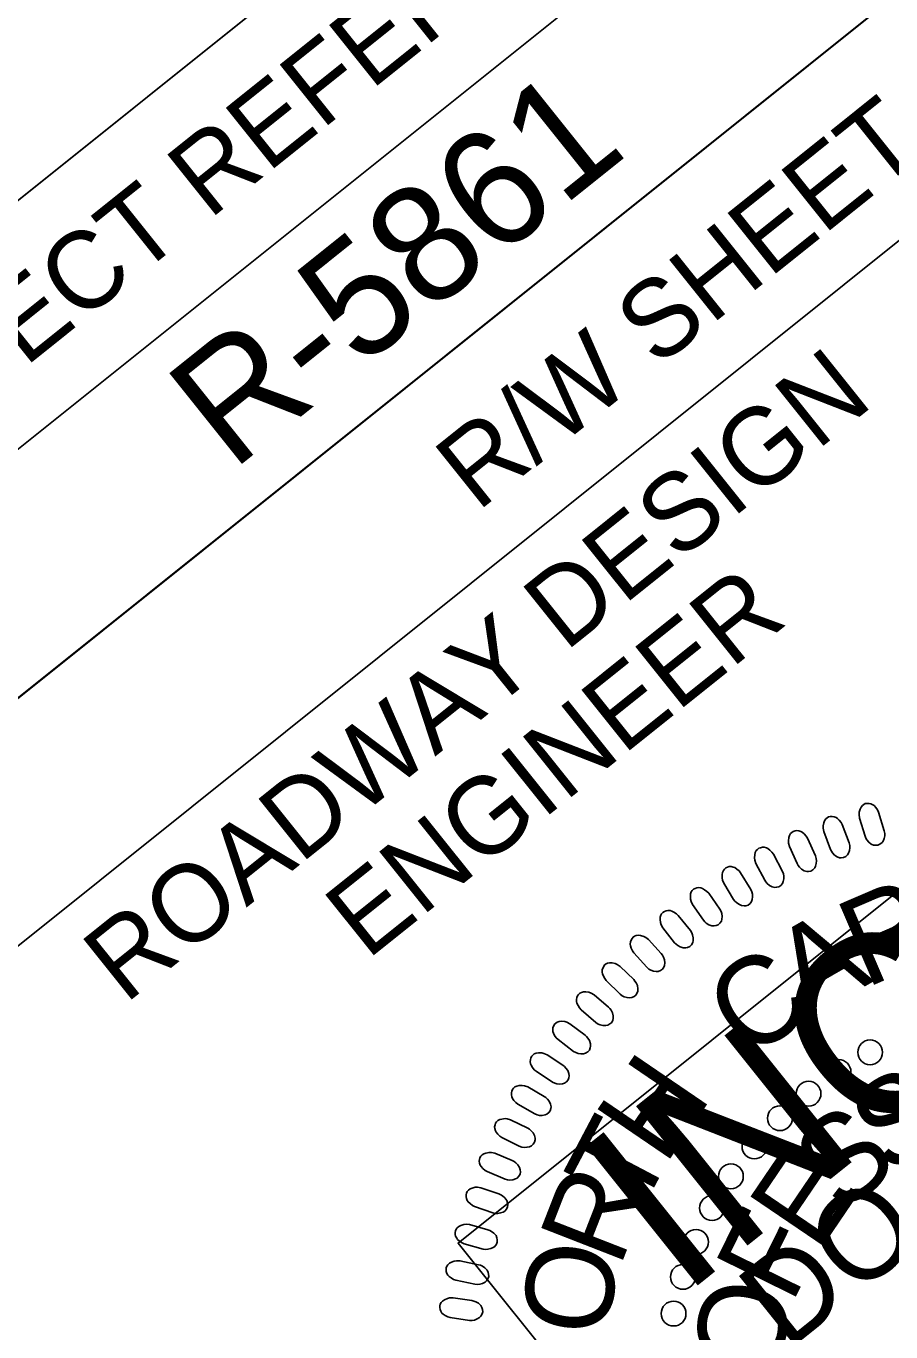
# Model space of a CAD drawing. Extents: x 472510 to 474509, y 505091 to 506998.
# Drawn here: x 473706 to 473761.9, y 506800.9 to 506885.2 of the extents above; entities that cross this region are included whole.
import ezdxf

# ---------------------------------------------------------------- set-up
doc = ezdxf.new("R2010")
doc.units = 0
for name, color, linetype in [('Sheet Data Field CELL', 7, 'Continuous'), ('Sheet PE Seal Cell', 7, 'Continuous'), ('Sheet Plan CELL', 7, 'Continuous'), ('Sheet Sticker Incomplete CELL', 7, 'Continuous')]:
    doc.layers.add(name, color=color, linetype=linetype)

msp = doc.modelspace()

# ---------------------------------------------------------------- linework, layer by layer
at = {"layer": 'Sheet PE Seal Cell'}
for points in [[(473760.213, 506832.902), (473759.853, 506834.074), (473759.824, 506834.295), (473759.833, 506834.444), (473759.891, 506834.639), (473759.952, 506834.773), (473760.035, 506834.882), (473760.124, 506834.95), (473760.225, 506835.003), (473760.338, 506835.016), (473760.461, 506835.023), (473760.579, 506834.996), (473760.708, 506834.931), (473760.789, 506834.873), (473760.897, 506834.75), (473761.007, 506834.596), (473761.075, 506834.45), (473761.451, 506833.25), (473761.478, 506833.081), (473761.477, 506832.935), (473761.438, 506832.756), (473761.372, 506832.589), (473761.303, 506832.485), (473761.169, 506832.382), (473761.032, 506832.319), (473760.878, 506832.313), (473760.763, 506832.33), (473760.612, 506832.388), (473760.449, 506832.516), (473760.331, 506832.667), (473760.265, 506832.783)], [(473757.971, 506832.049), (473757.538, 506833.197), (473757.496, 506833.416), (473757.496, 506833.564), (473757.54, 506833.763), (473757.593, 506833.899), (473757.669, 506834.014), (473757.753, 506834.088), (473757.851, 506834.146), (473757.963, 506834.167), (473758.086, 506834.181), (473758.205, 506834.162), (473758.338, 506834.106), (473758.422, 506834.052), (473758.538, 506833.936), (473758.657, 506833.789), (473758.734, 506833.648), (473759.184, 506832.474), (473759.224, 506832.308), (473759.23, 506832.161), (473759.203, 506831.98), (473759.147, 506831.81), (473759.084, 506831.701), (473758.959, 506831.59), (473758.825, 506831.519), (473758.672, 506831.503), (473758.556, 506831.513), (473758.402, 506831.561), (473758.231, 506831.678), (473758.104, 506831.822), (473758.031, 506831.933)], [(473755.826, 506831.129), (473755.321, 506832.247), (473755.266, 506832.462), (473755.256, 506832.611), (473755.288, 506832.812), (473755.332, 506832.952), (473755.401, 506833.07), (473755.48, 506833.15), (473755.574, 506833.215), (473755.685, 506833.242), (473755.806, 506833.264), (473755.926, 506833.252), (473756.062, 506833.204), (473756.149, 506833.156), (473756.273, 506833.047), (473756.401, 506832.908), (473756.488, 506832.772), (473757.01, 506831.629), (473757.059, 506831.466), (473757.075, 506831.32), (473757.059, 506831.138), (473757.014, 506830.964), (473756.959, 506830.851), (473756.84, 506830.732), (473756.712, 506830.653), (473756.559, 506830.628), (473756.443, 506830.63), (473756.287, 506830.669), (473756.107, 506830.774), (473755.973, 506830.911), (473755.892, 506831.016)], [(473753.729, 506830.058), (473753.157, 506831.143), (473753.087, 506831.354), (473753.068, 506831.502), (473753.088, 506831.704), (473753.123, 506831.846), (473753.184, 506831.969), (473753.258, 506832.053), (473753.348, 506832.124), (473753.456, 506832.158), (473753.576, 506832.188), (473753.697, 506832.184), (473753.836, 506832.144), (473753.926, 506832.102), (473754.055, 506832.001), (473754.192, 506831.87), (473754.287, 506831.739), (473754.881, 506830.632), (473754.939, 506830.472), (473754.965, 506830.327), (473754.96, 506830.144), (473754.926, 506829.968), (473754.878, 506829.853), (473754.767, 506829.726), (473754.644, 506829.639), (473754.494, 506829.604), (473754.378, 506829.6), (473754.219, 506829.628), (473754.034, 506829.723), (473753.89, 506829.849), (473753.803, 506829.951)], [(473751.724, 506828.82), (473751.084, 506829.866), (473751.001, 506830.073), (473750.973, 506830.219), (473750.98, 506830.422), (473751.006, 506830.567), (473751.06, 506830.693), (473751.128, 506830.782), (473751.214, 506830.858), (473751.32, 506830.899), (473751.437, 506830.936), (473751.558, 506830.939), (473751.699, 506830.909), (473751.792, 506830.872), (473751.928, 506830.78), (473752.072, 506830.657), (473752.174, 506830.533), (473752.837, 506829.465), (473752.906, 506829.309), (473752.94, 506829.167), (473752.947, 506828.984), (473752.924, 506828.806), (473752.883, 506828.687), (473752.78, 506828.554), (473752.663, 506828.459), (473752.515, 506828.415), (473752.4, 506828.403), (473752.239, 506828.421), (473752.048, 506828.504), (473751.898, 506828.622), (473751.804, 506828.717)], [(473749.77, 506827.48), (473749.065, 506828.485), (473748.97, 506828.686), (473748.933, 506828.83), (473748.927, 506829.033), (473748.944, 506829.179), (473748.99, 506829.309), (473749.053, 506829.401), (473749.133, 506829.482), (473749.236, 506829.53), (473749.351, 506829.574), (473749.471, 506829.586), (473749.614, 506829.564), (473749.709, 506829.533), (473749.85, 506829.449), (473750.002, 506829.337), (473750.112, 506829.219), (473750.84, 506828.194), (473750.919, 506828.043), (473750.962, 506827.903), (473750.98, 506827.721), (473750.969, 506827.542), (473750.935, 506827.421), (473750.841, 506827.281), (473750.73, 506827.179), (473750.585, 506827.126), (473750.47, 506827.107), (473750.309, 506827.116), (473750.114, 506827.186), (473749.956, 506827.294), (473749.857, 506827.383)], [(473747.912, 506826.027), (473747.145, 506826.985), (473747.038, 506827.18), (473746.991, 506827.322), (473746.973, 506827.524), (473746.98, 506827.67), (473747.018, 506827.803), (473747.075, 506827.899), (473747.15, 506827.985), (473747.25, 506828.039), (473747.362, 506828.091), (473747.481, 506828.109), (473747.625, 506828.097), (473747.722, 506828.071), (473747.868, 506827.997), (473748.027, 506827.894), (473748.144, 506827.783), (473748.934, 506826.807), (473749.023, 506826.661), (473749.075, 506826.523), (473749.105, 506826.343), (473749.105, 506826.163), (473749.078, 506826.041), (473748.993, 506825.896), (473748.889, 506825.787), (473748.747, 506825.725), (473748.635, 506825.698), (473748.473, 506825.696), (473748.273, 506825.755), (473748.109, 506825.853), (473748.004, 506825.935)], [(473747.047, 506825.323), (473746.222, 506826.231), (473746.046, 506826.368), (473745.914, 506826.436), (473745.717, 506826.487), (473745.571, 506826.503), (473745.434, 506826.486), (473745.33, 506826.446), (473745.234, 506826.384), (473745.165, 506826.294), (473745.096, 506826.192), (473745.058, 506826.077), (473745.048, 506825.933), (473745.058, 506825.834), (473745.108, 506825.678), (473745.185, 506825.505), (473745.275, 506825.372), (473746.115, 506824.437), (473746.245, 506824.326), (473746.373, 506824.253), (473746.546, 506824.195), (473746.723, 506824.167), (473746.849, 506824.173), (473747.006, 506824.235), (473747.13, 506824.32), (473747.213, 506824.451), (473747.257, 506824.558), (473747.284, 506824.717), (473747.259, 506824.923), (473747.187, 506825.101), (473747.123, 506825.218)], [(473745.269, 506823.641), (473744.389, 506824.496), (473744.206, 506824.622), (473744.069, 506824.681), (473743.869, 506824.719), (473743.723, 506824.726), (473743.588, 506824.701), (473743.486, 506824.653), (473743.393, 506824.587), (473743.33, 506824.492), (473743.268, 506824.386), (473743.238, 506824.269), (473743.237, 506824.125), (473743.253, 506824.026), (473743.313, 506823.874), (473743.4, 506823.706), (473743.499, 506823.579), (473744.395, 506822.698), (473744.533, 506822.596), (473744.664, 506822.531), (473744.841, 506822.484), (473745.019, 506822.467), (473745.144, 506822.482), (473745.297, 506822.552), (473745.415, 506822.646), (473745.491, 506822.781), (473745.528, 506822.891), (473745.545, 506823.051), (473745.506, 506823.255), (473745.424, 506823.428), (473745.352, 506823.54)], [(473743.64, 506821.866), (473742.709, 506822.663), (473742.518, 506822.778), (473742.377, 506822.829), (473742.175, 506822.854), (473742.029, 506822.851), (473741.896, 506822.818), (473741.797, 506822.764), (473741.709, 506822.692), (473741.651, 506822.594), (473741.597, 506822.484), (473741.574, 506822.365), (473741.581, 506822.22), (473741.603, 506822.123), (473741.674, 506821.975), (473741.771, 506821.813), (473741.877, 506821.692), (473742.827, 506820.87), (473742.971, 506820.776), (473743.106, 506820.72), (473743.286, 506820.684), (473743.465, 506820.679), (473743.589, 506820.701), (473743.736, 506820.781), (473743.848, 506820.882), (473743.915, 506821.021), (473743.945, 506821.133), (473743.952, 506821.295), (473743.901, 506821.496), (473743.808, 506821.663), (473743.729, 506821.77)], [(473742.135, 506820.057), (473741.155, 506820.794), (473740.958, 506820.896), (473740.814, 506820.939), (473740.611, 506820.951), (473740.466, 506820.939), (473740.334, 506820.897), (473740.239, 506820.838), (473740.156, 506820.76), (473740.104, 506820.659), (473740.057, 506820.545), (473740.042, 506820.425), (473740.058, 506820.282), (473740.086, 506820.186), (473740.165, 506820.042), (473740.273, 506819.887), (473740.386, 506819.773), (473741.387, 506819.012), (473741.535, 506818.927), (473741.674, 506818.88), (473741.856, 506818.855), (473742.035, 506818.861), (473742.156, 506818.891), (473742.299, 506818.98), (473742.405, 506819.088), (473742.463, 506819.231), (473742.486, 506819.345), (473742.482, 506819.506), (473742.419, 506819.704), (473742.316, 506819.866), (473742.23, 506819.967)], [(473740.701, 506818.114), (473739.677, 506818.788), (473739.473, 506818.878), (473739.328, 506818.911), (473739.125, 506818.911), (473738.979, 506818.89), (473738.851, 506818.84), (473738.76, 506818.775), (473738.682, 506818.692), (473738.636, 506818.587), (473738.596, 506818.471), (473738.588, 506818.351), (473738.614, 506818.209), (473738.648, 506818.114), (473738.736, 506817.976), (473738.853, 506817.827), (473738.974, 506817.721), (473740.02, 506817.024), (473740.174, 506816.95), (473740.315, 506816.91), (473740.497, 506816.897), (473740.676, 506816.914), (473740.796, 506816.952), (473740.932, 506817.05), (473741.031, 506817.164), (473741.08, 506817.311), (473741.096, 506817.426), (473741.082, 506817.586), (473741.006, 506817.78), (473740.893, 506817.934), (473740.801, 506818.031)], [(473739.493, 506816.102), (473738.428, 506816.71), (473738.219, 506816.787), (473738.072, 506816.811), (473737.869, 506816.798), (473737.726, 506816.768), (473737.601, 506816.71), (473737.514, 506816.639), (473737.442, 506816.551), (473737.403, 506816.444), (473737.37, 506816.325), (473737.37, 506816.205), (473737.404, 506816.064), (473737.444, 506815.973), (473737.54, 506815.84), (473737.667, 506815.699), (473737.794, 506815.601), (473738.881, 506814.971), (473739.039, 506814.906), (473739.183, 506814.876), (473739.366, 506814.874), (473739.543, 506814.902), (473739.661, 506814.947), (473739.791, 506815.054), (473739.882, 506815.174), (473739.921, 506815.323), (473739.93, 506815.439), (473739.906, 506815.599), (473739.819, 506815.787), (473739.696, 506815.934), (473739.598, 506816.025)], [(473738.423, 506814.05), (473737.322, 506814.591), (473737.109, 506814.654), (473736.96, 506814.669), (473736.758, 506814.643), (473736.617, 506814.604), (473736.496, 506814.538), (473736.414, 506814.462), (473736.347, 506814.37), (473736.315, 506814.261), (473736.289, 506814.14), (473736.297, 506814.02), (473736.34, 506813.882), (473736.386, 506813.793), (473736.49, 506813.667), (473736.625, 506813.534), (473736.758, 506813.443), (473737.883, 506812.884), (473738.045, 506812.828), (473738.191, 506812.807), (473738.373, 506812.818), (473738.548, 506812.857), (473738.662, 506812.909), (473738.785, 506813.023), (473738.869, 506813.149), (473738.899, 506813.301), (473738.9, 506813.416), (473738.867, 506813.574), (473738.768, 506813.756), (473738.636, 506813.896), (473738.533, 506813.98)], [(473737.43, 506811.957), (473736.297, 506812.427), (473736.08, 506812.477), (473735.932, 506812.483), (473735.732, 506812.444), (473735.593, 506812.396), (473735.476, 506812.324), (473735.4, 506812.242), (473735.338, 506812.146), (473735.313, 506812.035), (473735.295, 506811.913), (473735.31, 506811.793), (473735.362, 506811.658), (473735.413, 506811.573), (473735.525, 506811.453), (473735.668, 506811.329), (473735.807, 506811.247), (473736.965, 506810.758), (473737.13, 506810.714), (473737.276, 506810.702), (473737.457, 506810.724), (473737.63, 506810.774), (473737.741, 506810.833), (473737.857, 506810.955), (473737.932, 506811.085), (473737.953, 506811.238), (473737.947, 506811.354), (473737.903, 506811.51), (473737.792, 506811.685), (473737.653, 506811.817), (473737.544, 506811.894)], [(473736.569, 506809.805), (473735.409, 506810.203), (473735.189, 506810.239), (473735.04, 506810.235), (473734.843, 506810.185), (473734.708, 506810.128), (473734.596, 506810.048), (473734.524, 506809.962), (473734.469, 506809.862), (473734.451, 506809.749), (473734.441, 506809.627), (473734.463, 506809.509), (473734.524, 506809.377), (473734.58, 506809.294), (473734.699, 506809.182), (473734.85, 506809.068), (473734.994, 506808.994), (473736.18, 506808.579), (473736.347, 506808.545), (473736.494, 506808.542), (473736.674, 506808.576), (473736.842, 506808.636), (473736.949, 506808.702), (473737.057, 506808.831), (473737.124, 506808.966), (473737.135, 506809.121), (473737.122, 506809.236), (473737.069, 506809.388), (473736.947, 506809.556), (473736.799, 506809.678), (473736.687, 506809.749)], [(473735.853, 506807.497), (473734.67, 506807.822), (473734.449, 506807.844), (473734.3, 506807.831), (473734.107, 506807.767), (473733.975, 506807.702), (473733.869, 506807.615), (473733.802, 506807.525), (473733.754, 506807.422), (473733.743, 506807.309), (473733.741, 506807.186), (473733.77, 506807.069), (473733.839, 506806.942), (473733.9, 506806.863), (473734.027, 506806.758), (473734.184, 506806.653), (473734.332, 506806.589), (473735.541, 506806.249), (473735.711, 506806.226), (473735.858, 506806.232), (473736.035, 506806.276), (473736.199, 506806.348), (473736.303, 506806.42), (473736.401, 506806.556), (473736.46, 506806.695), (473736.461, 506806.85), (473736.441, 506806.963), (473736.379, 506807.113), (473736.246, 506807.273), (473736.091, 506807.385), (473735.974, 506807.449)], [(473735.253, 506805.238), (473734.052, 506805.487), (473733.83, 506805.495), (473733.682, 506805.473), (473733.494, 506805.398), (473733.366, 506805.325), (473733.265, 506805.231), (473733.205, 506805.137), (473733.163, 506805.031), (473733.159, 506804.917), (473733.165, 506804.794), (473733.201, 506804.679), (473733.278, 506804.556), (473733.344, 506804.482), (473733.477, 506804.385), (473733.64, 506804.29), (473733.792, 506804.235), (473735.02, 506803.972), (473735.191, 506803.96), (473735.337, 506803.976), (473735.511, 506804.031), (473735.671, 506804.112), (473735.769, 506804.191), (473735.859, 506804.333), (473735.909, 506804.475), (473735.9, 506804.63), (473735.873, 506804.742), (473735.801, 506804.887), (473735.66, 506805.038), (473735.498, 506805.14), (473735.377, 506805.196)], [(473734.819, 506802.919), (473733.605, 506803.093), (473733.382, 506803.087), (473733.236, 506803.055), (473733.052, 506802.968), (473732.93, 506802.888), (473732.835, 506802.788), (473732.781, 506802.69), (473732.745, 506802.582), (473732.749, 506802.468), (473732.762, 506802.345), (473732.806, 506802.233), (473732.89, 506802.115), (473732.96, 506802.045), (473733.099, 506801.957), (473733.268, 506801.873), (473733.422, 506801.828), (473734.666, 506801.642), (473734.837, 506801.64), (473734.981, 506801.665), (473735.152, 506801.731), (473735.307, 506801.823), (473735.4, 506801.907), (473735.481, 506802.054), (473735.522, 506802.2), (473735.503, 506802.353), (473735.469, 506802.464), (473735.388, 506802.604), (473735.238, 506802.746), (473735.069, 506802.838), (473734.945, 506802.886)]]:
    msp.add_lwpolyline(points, close=True, dxfattribs=at)
for centre in [(473760.538, 506818.948), (473758.498, 506817.673), (473756.558, 506816.275), (473754.711, 506814.696), (473753.064, 506812.868), (473751.546, 506810.94), (473750.328, 506808.894), (473749.293, 506806.707), (473748.447, 506804.45), (473747.844, 506802.08)]:
    msp.add_circle(centre, 0.801, dxfattribs=at)
at = {"layer": 'Sheet Plan CELL'}
for p, q in [((473677.092, 506835.141), (473833.287, 506960.133)), ((473684.936, 506825.36), (473841.098, 506950.373)), ((473684.936, 506825.36), (473841.098, 506950.373))]:
    msp.add_line(p, q, dxfattribs=at)
for points in [[(473825.475, 506969.955), (472654.329, 506032.655), (473310.422, 505212.874), (474481.549, 506150.157)], [(473669.26, 506844.947), (473825.475, 506969.955), (473841.098, 506950.373), (473684.936, 506825.36)], [(473692.738, 506815.611), (473770.852, 506878.127), (473841.155, 506790.284), (473763.036, 506727.795)]]:
    msp.add_lwpolyline(points, close=True, dxfattribs=at)
at = {"layer": 'Sheet Sticker Incomplete CELL'}
msp.add_lwpolyline([(473748.615, 506788.284), (473733.931, 506806.631), (473848.7, 506898.484), (473863.384, 506880.137)], close=True, dxfattribs=at)

# ---------------------------------------------------------------- texts
at = {"layer": 'Sheet Data Field CELL'}
msp.add_text('R-5861', height=7.5, rotation=38.67123, dxfattribs=at).set_placement((473719.329, 506856.424))
at = {"layer": 'Sheet PE Seal Cell'}
for s, rotation, p in [('R', 23.28019, (473760.221, 506823.06)), ('A', 29.76954, (473756.441, 506821.052)), ('C', 36.2589, (473752.738, 506818.356)), ('H', 55.72697, (473747.275, 506811.571)), ('S', 32.02046, (473761.667, 506810.911)), ('T', 62.21633, (473745.674, 506808.483)), ('S', 39.96025, (473758.716, 506808.419)), ('E', 55.83985, (473757.155, 506805.941)), ('R', 68.70569, (473744.358, 506804.973)), ('F', 63.77965, (473755.47, 506802.621)), ('O', 81.6844, (473743.537, 506800.437)), ('O', 79.65924, (473754.545, 506797.861))]:
    msp.add_text(s, height=5.669, rotation=rotation, dxfattribs=at).set_placement(p)
at = {"layer": 'Sheet Plan CELL'}
for s, p in [('PROJECT REFERENCE NO.', (473692.044, 506852.007)), ('R/W SHEET NO.', (473735.179, 506853.804)), ('ROADWAY DESIGN', (473712.427, 506822.018)), ('ENGINEER', (473728.057, 506824.873))]:
    msp.add_text(s, height=5.0001, rotation=38.67123, dxfattribs=at).set_placement(p)
at = {"layer": 'Sheet Sticker Incomplete CELL'}
for s, height, p in [('INCOMPLETE PLANS', 11.52, (473748.292, 506803.011)), ('DO NOT USE FOR R/W ACQUISITION', 5.76, (473755.172, 506799.615))]:
    msp.add_text(s, height=height, rotation=38.67122, dxfattribs=at).set_placement(p)

doc.saveas('drawing.dxf')
